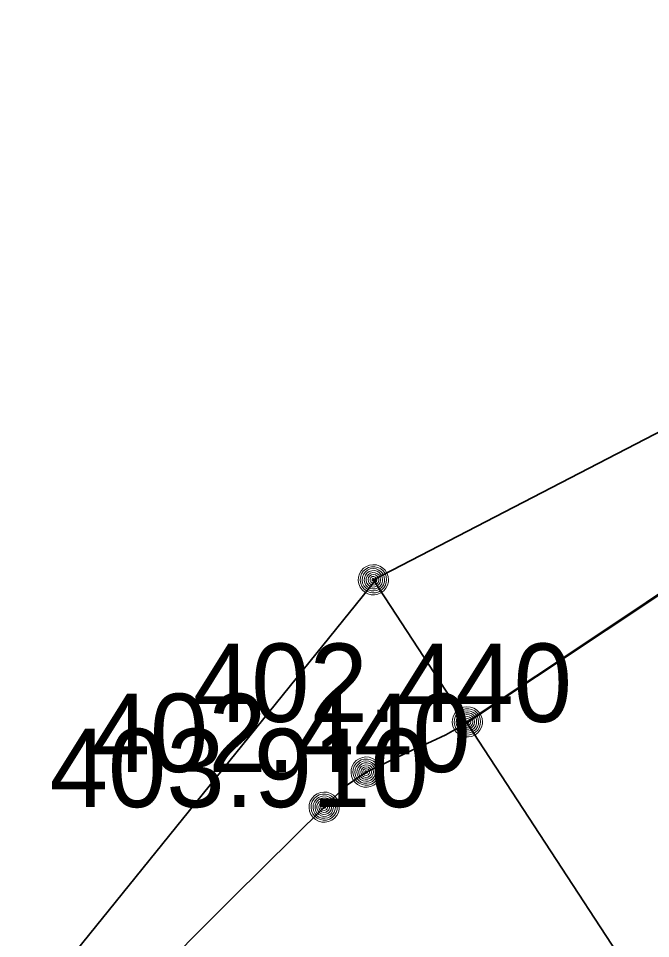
# Model space of a CAD drawing. Extents: x -873619 to -867639, y -1015082 to -1012326.
# Drawn here: x -867987.24 to -867977.57, y -1012706.79 to -1012692.71 of the extents above; entities that cross this region are included whole.
import ezdxf

# ---------------------------------------------------------------- set-up
doc = ezdxf.new("R2010")
doc.units = 0
doc.header["$LTSCALE"] = 0.44
for name, color, linetype, lineweight in [('1', 7, 'Continuous', 13), ('21', 7, 'Continuous', 35), ('25', 7, 'Continuous', 13), ('26', 7, 'Continuous', 53)]:
    doc.layers.add(name, color=color, linetype=linetype, lineweight=lineweight)

msp = doc.modelspace()

# ---------------------------------------------------------------- linework, layer by layer
at = {"layer": '1'}
for points in [[(-867980.141, -1012703.476), (-867980.147, -1012703.424), (-867980.164, -1012703.374), (-867980.193, -1012703.33), (-867980.23, -1012703.293), (-867980.275, -1012703.266), (-867980.325, -1012703.249), (-867980.378, -1012703.245), (-867980.429, -1012703.252), (-867980.478, -1012703.271), (-867980.522, -1012703.3), (-867980.558, -1012703.339), (-867980.584, -1012703.384), (-867980.6, -1012703.435), (-867980.603, -1012703.487), (-867980.595, -1012703.539), (-867980.575, -1012703.588), (-867980.544, -1012703.631), (-867980.505, -1012703.665), (-867980.459, -1012703.691), (-867980.407, -1012703.705), (-867980.355, -1012703.707), (-867980.304, -1012703.697), (-867980.255, -1012703.676), (-867980.213, -1012703.645), (-867980.179, -1012703.604), (-867980.155, -1012703.558), (-867980.142, -1012703.507)], [(-867980.171, -1012703.476), (-867980.177, -1012703.427), (-867980.194, -1012703.381), (-867980.222, -1012703.341), (-867980.259, -1012703.309), (-867980.303, -1012703.287), (-867980.351, -1012703.276), (-867980.4, -1012703.276), (-867980.446, -1012703.289), (-867980.49, -1012703.313), (-867980.526, -1012703.346), (-867980.553, -1012703.387), (-867980.569, -1012703.434), (-867980.573, -1012703.483), (-867980.566, -1012703.531), (-867980.547, -1012703.576), (-867980.517, -1012703.616), (-867980.478, -1012703.647), (-867980.434, -1012703.667), (-867980.387, -1012703.677), (-867980.338, -1012703.675), (-867980.291, -1012703.66), (-867980.248, -1012703.635), (-867980.213, -1012703.601), (-867980.188, -1012703.559), (-867980.174, -1012703.512)], [(-867980.201, -1012703.476), (-867980.206, -1012703.431), (-867980.223, -1012703.389), (-867980.252, -1012703.354), (-867980.288, -1012703.327), (-867980.33, -1012703.31), (-867980.375, -1012703.305), (-867980.419, -1012703.311), (-867980.461, -1012703.33), (-867980.495, -1012703.358), (-867980.522, -1012703.395), (-867980.539, -1012703.437), (-867980.543, -1012703.482), (-867980.536, -1012703.527), (-867980.517, -1012703.568), (-867980.488, -1012703.602), (-867980.451, -1012703.628), (-867980.407, -1012703.644), (-867980.363, -1012703.647), (-867980.318, -1012703.639), (-867980.277, -1012703.619), (-867980.244, -1012703.59), (-867980.218, -1012703.552), (-867980.204, -1012703.509)], [(-867980.231, -1012703.476), (-867980.235, -1012703.435), (-867980.254, -1012703.398), (-867980.281, -1012703.367), (-867980.316, -1012703.346), (-867980.356, -1012703.335), (-867980.397, -1012703.337), (-867980.436, -1012703.35), (-867980.47, -1012703.374), (-867980.495, -1012703.406), (-867980.51, -1012703.444), (-867980.512, -1012703.485), (-867980.505, -1012703.525), (-867980.485, -1012703.561), (-867980.456, -1012703.59), (-867980.419, -1012703.609), (-867980.379, -1012703.617), (-867980.338, -1012703.613), (-867980.299, -1012703.598), (-867980.267, -1012703.572), (-867980.245, -1012703.538), (-867980.232, -1012703.499)], [(-867980.261, -1012703.476), (-867980.266, -1012703.44), (-867980.284, -1012703.408), (-867980.309, -1012703.383), (-867980.343, -1012703.368), (-867980.38, -1012703.365), (-867980.414, -1012703.373), (-867980.446, -1012703.393), (-867980.468, -1012703.421), (-867980.482, -1012703.455), (-867980.482, -1012703.492), (-867980.471, -1012703.527), (-867980.45, -1012703.556), (-867980.419, -1012703.577), (-867980.385, -1012703.587), (-867980.348, -1012703.585), (-867980.314, -1012703.571), (-867980.287, -1012703.548), (-867980.267, -1012703.516), (-867980.261, -1012703.481)], [(-867980.291, -1012703.476), (-867980.296, -1012703.445), (-867980.313, -1012703.419), (-867980.338, -1012703.402), (-867980.369, -1012703.395), (-867980.4, -1012703.399), (-867980.427, -1012703.416), (-867980.445, -1012703.44), (-867980.453, -1012703.471), (-867980.449, -1012703.501), (-867980.434, -1012703.529), (-867980.409, -1012703.548), (-867980.38, -1012703.557), (-867980.348, -1012703.554), (-867980.321, -1012703.54), (-867980.301, -1012703.516), (-867980.291, -1012703.487)], [(-867980.321, -1012703.476), (-867980.326, -1012703.452), (-867980.343, -1012703.434), (-867980.365, -1012703.425), (-867980.39, -1012703.428), (-867980.411, -1012703.442), (-867980.422, -1012703.464), (-867980.422, -1012703.489), (-867980.409, -1012703.51), (-867980.39, -1012703.524), (-867980.365, -1012703.527), (-867980.342, -1012703.518), (-867980.326, -1012703.5)], [(-867980.351, -1012703.476), (-867980.356, -1012703.461), (-867980.37, -1012703.455), (-867980.386, -1012703.459), (-867980.392, -1012703.473), (-867980.389, -1012703.488), (-867980.375, -1012703.497), (-867980.36, -1012703.494), (-867980.351, -1012703.482)], [(-867981.69, -1012704.244), (-867981.696, -1012704.192), (-867981.713, -1012704.142), (-867981.742, -1012704.098), (-867981.779, -1012704.061), (-867981.824, -1012704.034), (-867981.874, -1012704.017), (-867981.927, -1012704.013), (-867981.978, -1012704.02), (-867982.027, -1012704.039), (-867982.071, -1012704.068), (-867982.107, -1012704.107), (-867982.133, -1012704.152), (-867982.149, -1012704.203), (-867982.152, -1012704.255), (-867982.144, -1012704.307), (-867982.124, -1012704.356), (-867982.093, -1012704.399), (-867982.054, -1012704.433), (-867982.008, -1012704.459), (-867981.956, -1012704.473), (-867981.904, -1012704.475), (-867981.853, -1012704.465), (-867981.804, -1012704.444), (-867981.762, -1012704.413), (-867981.728, -1012704.372), (-867981.704, -1012704.326), (-867981.691, -1012704.275)], [(-867981.72, -1012704.244), (-867981.726, -1012704.195), (-867981.743, -1012704.149), (-867981.771, -1012704.109), (-867981.808, -1012704.077), (-867981.852, -1012704.055), (-867981.9, -1012704.044), (-867981.949, -1012704.044), (-867981.995, -1012704.057), (-867982.039, -1012704.081), (-867982.075, -1012704.114), (-867982.102, -1012704.155), (-867982.118, -1012704.202), (-867982.122, -1012704.251), (-867982.115, -1012704.299), (-867982.096, -1012704.344), (-867982.066, -1012704.384), (-867982.027, -1012704.415), (-867981.983, -1012704.435), (-867981.936, -1012704.445), (-867981.887, -1012704.443), (-867981.84, -1012704.428), (-867981.797, -1012704.403), (-867981.762, -1012704.369), (-867981.737, -1012704.327), (-867981.723, -1012704.28)], [(-867981.75, -1012704.244), (-867981.755, -1012704.199), (-867981.772, -1012704.157), (-867981.801, -1012704.122), (-867981.837, -1012704.095), (-867981.879, -1012704.078), (-867981.924, -1012704.073), (-867981.968, -1012704.079), (-867982.01, -1012704.098), (-867982.044, -1012704.126), (-867982.071, -1012704.163), (-867982.088, -1012704.205), (-867982.092, -1012704.25), (-867982.085, -1012704.295), (-867982.066, -1012704.336), (-867982.037, -1012704.37), (-867982, -1012704.396), (-867981.956, -1012704.412), (-867981.912, -1012704.415), (-867981.867, -1012704.407), (-867981.826, -1012704.387), (-867981.793, -1012704.358), (-867981.767, -1012704.32), (-867981.753, -1012704.277)], [(-867981.78, -1012704.244), (-867981.784, -1012704.203), (-867981.803, -1012704.166), (-867981.83, -1012704.135), (-867981.865, -1012704.114), (-867981.905, -1012704.103), (-867981.946, -1012704.105), (-867981.985, -1012704.118), (-867982.019, -1012704.142), (-867982.044, -1012704.174), (-867982.059, -1012704.212), (-867982.061, -1012704.253), (-867982.054, -1012704.293), (-867982.034, -1012704.329), (-867982.005, -1012704.358), (-867981.968, -1012704.377), (-867981.928, -1012704.385), (-867981.887, -1012704.381), (-867981.848, -1012704.366), (-867981.816, -1012704.34), (-867981.794, -1012704.306), (-867981.781, -1012704.267)], [(-867981.809, -1012704.244), (-867981.815, -1012704.208), (-867981.833, -1012704.176), (-867981.858, -1012704.151), (-867981.892, -1012704.136), (-867981.929, -1012704.133), (-867981.963, -1012704.141), (-867981.995, -1012704.161), (-867982.017, -1012704.189), (-867982.031, -1012704.223), (-867982.031, -1012704.26), (-867982.02, -1012704.295), (-867981.999, -1012704.324), (-867981.968, -1012704.345), (-867981.934, -1012704.355), (-867981.897, -1012704.353), (-867981.863, -1012704.339), (-867981.836, -1012704.316), (-867981.816, -1012704.284), (-867981.809, -1012704.249)], [(-867981.84, -1012704.244), (-867981.845, -1012704.213), (-867981.862, -1012704.187), (-867981.887, -1012704.17), (-867981.918, -1012704.163), (-867981.949, -1012704.167), (-867981.976, -1012704.184), (-867981.994, -1012704.208), (-867982.002, -1012704.239), (-867981.998, -1012704.269), (-867981.983, -1012704.297), (-867981.958, -1012704.316), (-867981.929, -1012704.325), (-867981.897, -1012704.322), (-867981.87, -1012704.308), (-867981.85, -1012704.284), (-867981.84, -1012704.255)], [(-867981.87, -1012704.244), (-867981.875, -1012704.22), (-867981.892, -1012704.202), (-867981.914, -1012704.193), (-867981.939, -1012704.196), (-867981.96, -1012704.21), (-867981.971, -1012704.232), (-867981.971, -1012704.257), (-867981.958, -1012704.278), (-867981.939, -1012704.292), (-867981.914, -1012704.295), (-867981.891, -1012704.286), (-867981.875, -1012704.268)], [(-867981.9, -1012704.244), (-867981.905, -1012704.229), (-867981.919, -1012704.223), (-867981.934, -1012704.227), (-867981.941, -1012704.241), (-867981.938, -1012704.256), (-867981.924, -1012704.265), (-867981.909, -1012704.262), (-867981.9, -1012704.25)], [(-867982.331, -1012704.781), (-867982.338, -1012704.729), (-867982.355, -1012704.679), (-867982.384, -1012704.635), (-867982.421, -1012704.598), (-867982.466, -1012704.571), (-867982.516, -1012704.554), (-867982.569, -1012704.55), (-867982.62, -1012704.557), (-867982.669, -1012704.576), (-867982.713, -1012704.605), (-867982.749, -1012704.644), (-867982.775, -1012704.689), (-867982.791, -1012704.74), (-867982.794, -1012704.792), (-867982.786, -1012704.844), (-867982.766, -1012704.893), (-867982.735, -1012704.936), (-867982.696, -1012704.97), (-867982.65, -1012704.996), (-867982.598, -1012705.01), (-867982.546, -1012705.012), (-867982.495, -1012705.002), (-867982.446, -1012704.981), (-867982.404, -1012704.95), (-867982.37, -1012704.909), (-867982.346, -1012704.863), (-867982.333, -1012704.812)], [(-867982.362, -1012704.781), (-867982.368, -1012704.732), (-867982.385, -1012704.686), (-867982.413, -1012704.646), (-867982.45, -1012704.614), (-867982.494, -1012704.592), (-867982.542, -1012704.581), (-867982.591, -1012704.581), (-867982.637, -1012704.594), (-867982.681, -1012704.618), (-867982.717, -1012704.651), (-867982.744, -1012704.692), (-867982.76, -1012704.739), (-867982.764, -1012704.788), (-867982.757, -1012704.836), (-867982.738, -1012704.881), (-867982.708, -1012704.921), (-867982.669, -1012704.952), (-867982.625, -1012704.972), (-867982.578, -1012704.982), (-867982.529, -1012704.98), (-867982.482, -1012704.965), (-867982.439, -1012704.94), (-867982.404, -1012704.906), (-867982.379, -1012704.864), (-867982.365, -1012704.817)], [(-867982.392, -1012704.781), (-867982.397, -1012704.736), (-867982.414, -1012704.694), (-867982.443, -1012704.659), (-867982.478, -1012704.632), (-867982.521, -1012704.615), (-867982.566, -1012704.61), (-867982.61, -1012704.616), (-867982.652, -1012704.635), (-867982.686, -1012704.663), (-867982.713, -1012704.7), (-867982.73, -1012704.742), (-867982.733, -1012704.787), (-867982.727, -1012704.832), (-867982.708, -1012704.873), (-867982.679, -1012704.907), (-867982.642, -1012704.933), (-867982.598, -1012704.949), (-867982.554, -1012704.952), (-867982.509, -1012704.944), (-867982.468, -1012704.924), (-867982.434, -1012704.895), (-867982.409, -1012704.857), (-867982.395, -1012704.814)], [(-867982.422, -1012704.781), (-867982.426, -1012704.74), (-867982.445, -1012704.703), (-867982.472, -1012704.672), (-867982.507, -1012704.651), (-867982.547, -1012704.64), (-867982.588, -1012704.642), (-867982.627, -1012704.655), (-867982.661, -1012704.679), (-867982.686, -1012704.711), (-867982.701, -1012704.749), (-867982.703, -1012704.79), (-867982.696, -1012704.83), (-867982.676, -1012704.866), (-867982.647, -1012704.895), (-867982.61, -1012704.914), (-867982.57, -1012704.922), (-867982.529, -1012704.918), (-867982.49, -1012704.903), (-867982.458, -1012704.877), (-867982.436, -1012704.843), (-867982.423, -1012704.804)], [(-867982.451, -1012704.781), (-867982.456, -1012704.745), (-867982.475, -1012704.713), (-867982.5, -1012704.688), (-867982.534, -1012704.673), (-867982.571, -1012704.67), (-867982.605, -1012704.678), (-867982.637, -1012704.698), (-867982.659, -1012704.726), (-867982.673, -1012704.76), (-867982.673, -1012704.797), (-867982.662, -1012704.832), (-867982.641, -1012704.861), (-867982.61, -1012704.882), (-867982.576, -1012704.892), (-867982.539, -1012704.89), (-867982.505, -1012704.876), (-867982.478, -1012704.853), (-867982.458, -1012704.821), (-867982.451, -1012704.786)], [(-867982.482, -1012704.781), (-867982.487, -1012704.75), (-867982.504, -1012704.724), (-867982.529, -1012704.707), (-867982.559, -1012704.7), (-867982.591, -1012704.704), (-867982.618, -1012704.721), (-867982.636, -1012704.745), (-867982.644, -1012704.776), (-867982.64, -1012704.806), (-867982.625, -1012704.834), (-867982.6, -1012704.853), (-867982.571, -1012704.862), (-867982.539, -1012704.859), (-867982.512, -1012704.845), (-867982.492, -1012704.821), (-867982.482, -1012704.792)], [(-867982.512, -1012704.781), (-867982.517, -1012704.757), (-867982.534, -1012704.739), (-867982.556, -1012704.73), (-867982.581, -1012704.733), (-867982.602, -1012704.747), (-867982.613, -1012704.769), (-867982.613, -1012704.794), (-867982.6, -1012704.815), (-867982.581, -1012704.829), (-867982.556, -1012704.832), (-867982.532, -1012704.823), (-867982.517, -1012704.805)], [(-867982.542, -1012704.781), (-867982.547, -1012704.766), (-867982.561, -1012704.76), (-867982.576, -1012704.764), (-867982.583, -1012704.778), (-867982.58, -1012704.793), (-867982.566, -1012704.802), (-867982.551, -1012704.799), (-867982.542, -1012704.787)]]:
    msp.add_lwpolyline(points, close=True, dxfattribs=at)
at = {"layer": '21'}
for points in [[(-867964.04, -1012692.09), (-867981.81, -1012701.3), (-867981.801, -1012701.313)], [(-867976.269, -1012700.734), (-867980.372, -1012703.476), (-867980.525, -1012703.574), (-867980.7, -1012703.672), (-867980.923, -1012703.776), (-867981.042, -1012703.832), (-867981.216, -1012703.909), (-867981.726, -1012704.153), (-867981.921, -1012704.244), (-867982.235, -1012704.46), (-867982.563, -1012704.781), (-867983.959, -1012706.163), (-867985.368, -1012707.58)], [(-868007.52, -1012735.85), (-867995.258, -1012717.991), (-867981.769, -1012701.297)], [(-867981.801, -1012701.313), (-867966.749, -1012724.362), (-867954.427, -1012739.171)]]:
    msp.add_lwpolyline(points, dxfattribs=at)
at = {"layer": '25'}
for points in [[(-867981.579, -1012701.3), (-867981.585, -1012701.248), (-867981.602, -1012701.198), (-867981.631, -1012701.154), (-867981.668, -1012701.117), (-867981.713, -1012701.09), (-867981.763, -1012701.073), (-867981.816, -1012701.069), (-867981.868, -1012701.076), (-867981.917, -1012701.095), (-867981.96, -1012701.124), (-867981.996, -1012701.163), (-867982.022, -1012701.208), (-867982.038, -1012701.259), (-867982.041, -1012701.311), (-867982.033, -1012701.363), (-867982.013, -1012701.412), (-867981.982, -1012701.455), (-867981.943, -1012701.489), (-867981.897, -1012701.515), (-867981.846, -1012701.529), (-867981.793, -1012701.531), (-867981.742, -1012701.521), (-867981.694, -1012701.5), (-867981.651, -1012701.469), (-867981.617, -1012701.428), (-867981.593, -1012701.382), (-867981.581, -1012701.331)], [(-867981.609, -1012701.3), (-867981.615, -1012701.251), (-867981.632, -1012701.205), (-867981.66, -1012701.165), (-867981.697, -1012701.133), (-867981.741, -1012701.111), (-867981.789, -1012701.1), (-867981.838, -1012701.1), (-867981.885, -1012701.113), (-867981.928, -1012701.137), (-867981.964, -1012701.17), (-867981.991, -1012701.211), (-867982.007, -1012701.258), (-867982.011, -1012701.307), (-867982.004, -1012701.355), (-867981.985, -1012701.4), (-867981.955, -1012701.44), (-867981.917, -1012701.471), (-867981.873, -1012701.491), (-867981.825, -1012701.501), (-867981.776, -1012701.499), (-867981.729, -1012701.484), (-867981.686, -1012701.459), (-867981.652, -1012701.425), (-867981.626, -1012701.383), (-867981.612, -1012701.336)], [(-867981.639, -1012701.3), (-867981.645, -1012701.255), (-867981.662, -1012701.213), (-867981.69, -1012701.178), (-867981.726, -1012701.151), (-867981.768, -1012701.134), (-867981.813, -1012701.129), (-867981.858, -1012701.135), (-867981.899, -1012701.154), (-867981.934, -1012701.182), (-867981.961, -1012701.219), (-867981.977, -1012701.261), (-867981.981, -1012701.306), (-867981.974, -1012701.351), (-867981.955, -1012701.392), (-867981.926, -1012701.426), (-867981.889, -1012701.452), (-867981.846, -1012701.468), (-867981.801, -1012701.471), (-867981.756, -1012701.463), (-867981.716, -1012701.443), (-867981.682, -1012701.414), (-867981.656, -1012701.376), (-867981.642, -1012701.333)], [(-867981.669, -1012701.3), (-867981.674, -1012701.259), (-867981.692, -1012701.222), (-867981.719, -1012701.191), (-867981.754, -1012701.17), (-867981.794, -1012701.159), (-867981.835, -1012701.161), (-867981.874, -1012701.174), (-867981.908, -1012701.198), (-867981.933, -1012701.23), (-867981.948, -1012701.268), (-867981.951, -1012701.309), (-867981.943, -1012701.349), (-867981.923, -1012701.385), (-867981.894, -1012701.414), (-867981.857, -1012701.433), (-867981.817, -1012701.441), (-867981.776, -1012701.437), (-867981.738, -1012701.422), (-867981.706, -1012701.396), (-867981.683, -1012701.362), (-867981.67, -1012701.323)], [(-867981.699, -1012701.3), (-867981.704, -1012701.264), (-867981.722, -1012701.232), (-867981.748, -1012701.207), (-867981.782, -1012701.192), (-867981.818, -1012701.189), (-867981.853, -1012701.197), (-867981.884, -1012701.217), (-867981.907, -1012701.245), (-867981.92, -1012701.279), (-867981.92, -1012701.316), (-867981.909, -1012701.351), (-867981.888, -1012701.38), (-867981.858, -1012701.401), (-867981.823, -1012701.411), (-867981.786, -1012701.409), (-867981.752, -1012701.395), (-867981.725, -1012701.372), (-867981.706, -1012701.34), (-867981.699, -1012701.305)], [(-867981.729, -1012701.3), (-867981.734, -1012701.269), (-867981.751, -1012701.243), (-867981.777, -1012701.226), (-867981.807, -1012701.219), (-867981.838, -1012701.223), (-867981.865, -1012701.24), (-867981.883, -1012701.264), (-867981.891, -1012701.295), (-867981.887, -1012701.325), (-867981.872, -1012701.353), (-867981.848, -1012701.372), (-867981.818, -1012701.381), (-867981.787, -1012701.378), (-867981.759, -1012701.364), (-867981.739, -1012701.34), (-867981.729, -1012701.311)], [(-867981.759, -1012701.3), (-867981.764, -1012701.276), (-867981.781, -1012701.258), (-867981.804, -1012701.249), (-867981.828, -1012701.252), (-867981.849, -1012701.266), (-867981.86, -1012701.288), (-867981.86, -1012701.313), (-867981.848, -1012701.334), (-867981.828, -1012701.348), (-867981.803, -1012701.351), (-867981.78, -1012701.342), (-867981.764, -1012701.324)], [(-867981.789, -1012701.3), (-867981.794, -1012701.285), (-867981.809, -1012701.279), (-867981.824, -1012701.283), (-867981.831, -1012701.297), (-867981.827, -1012701.312), (-867981.814, -1012701.321), (-867981.799, -1012701.318), (-867981.789, -1012701.306)]]:
    msp.add_lwpolyline(points, close=True, dxfattribs=at)
at = {"layer": '26'}
msp.add_line((-867980.372, -1012703.476), (-867970.311, -1012696.771), dxfattribs=at)

# ---------------------------------------------------------------- texts
at = {"layer": '1'}
for s, p in [('402.440 ', (-867984.572, -1012703.476)), ('402.440 ', (-867986.121, -1012704.244)), ('403.910 ', (-867986.763, -1012704.781))]:
    msp.add_text(s, height=1.2, dxfattribs=at).set_placement(p)

doc.saveas('drawing.dxf')
